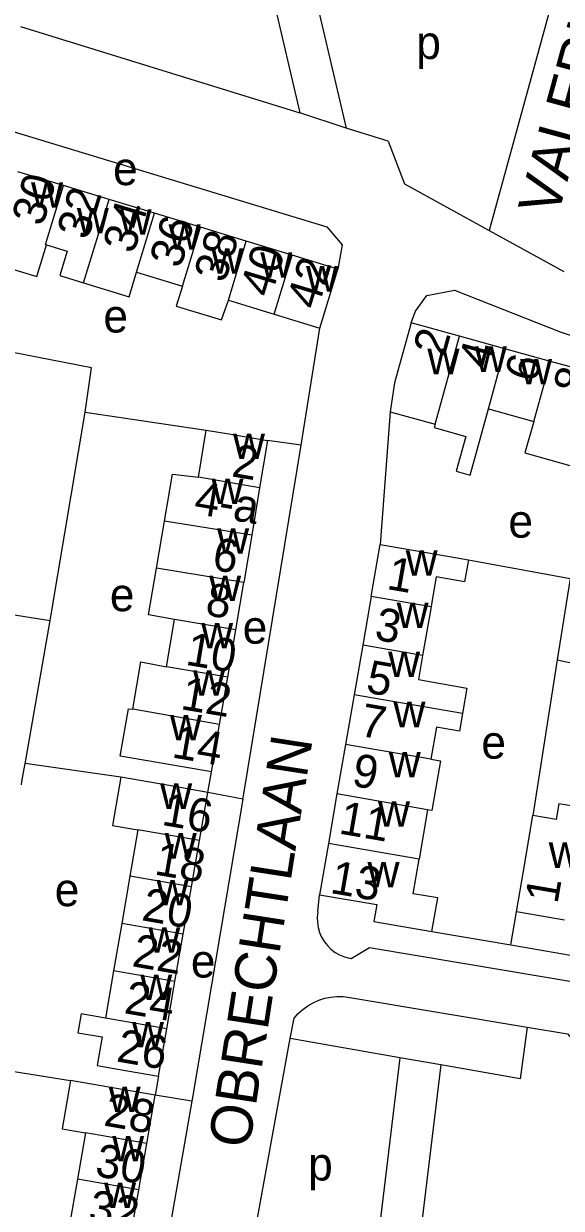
# Model space of a CAD drawing. Extents: x 159045 to 160918, y 380454 to 382516.
# Drawn here: x 160156.1 to 160221.1, y 380927 to 381070.1 of the extents above; entities that cross this region are included whole.
import ezdxf

# ---------------------------------------------------------------- set-up
doc = ezdxf.new("R2010")
doc.units = 0
for name, color, linetype in [('BLT_Basislijn', 7, 'Continuous'), ('BLT_Bebouwing', 7, 'Continuous'), ('BLT_Centroide', 7, 'Continuous'), ('BLT_Huisnummer', 7, 'Continuous'), ('BLT_Huisnummer_ tussenligend', 7, 'Continuous'), ('BLT_Huisnummer_reeks', 7, 'Continuous'), ('BLT_Onderverdeling_panden', 7, 'Continuous'), ('BLT_Straatnaam', 7, 'Continuous')]:
    doc.layers.add(name, color=color, linetype=linetype)

msp = doc.modelspace()

# ---------------------------------------------------------------- linework, layer by layer
at = {"layer": 'BLT_Basislijn'}
for p, q in [((160183.61, 381084.54), (160189.49, 381059.35)), ((160188.66, 381084.9), (160195.06, 381057.51)), ((160220.55, 381075.05), (160212.36, 381045.16)), ((160155.74, 381069.81), (160189.49, 381059.35)), ((160195.06, 381057.51), (160189.49, 381059.35)), ((160200.15, 381055.96), (160195.06, 381057.51)), ((160212.36, 381045.16), (160221.37, 381040.19)), ((160189.62, 381019.2), (160191.91, 381033.36)), ((160163.53, 381023.19), (160178.17, 381021.03)), ((160200.38, 381023.25), (160199.19, 381007.19)), ((160189.62, 381019.2), (160185.58, 381019.79)), ((160209.85, 381005.36), (160222.14, 381003.08)), ((160222.14, 381003.08), (160220.58, 380993.28)), ((160147.11, 380999.97), (160159.31, 380998)), ((160220.58, 380993.28), (160217.63, 380974.45)), ((160167.85, 380979.07), (160156.28, 380980.74)), ((160178.36, 380977.25), (160178.8, 380979.72)), ((160182.59, 380976.44), (160178.36, 380977.25)), ((160191.64, 380962.79), (160191.85, 380964.88)), ((160214.96, 380958.81), (160215.64, 380962.8)), ((160205.43, 380960.45), (160214.96, 380958.81)), ((160214.96, 380958.81), (160266.2, 380949.96)), ((160195.53, 380952.46), (160216.94, 380948.87)), ((160188.31, 380947.52), (160188.78, 380949.96)), ((160188.1, 380946.43), (160188.31, 380947.52)), ((160201.57, 380945.18), (160188.31, 380947.52)), ((160201.57, 380945.18), (160198.45, 380919.42)), ((160206.5, 380944.31), (160201.57, 380945.18)), ((160149.99, 380944.28), (160161.78, 380942.42)), ((160172.41, 380942.95), (160172, 380940.65)), ((160176.43, 380939.93), (160169.46, 380899.95)), ((160176.43, 380939.93), (160172, 380940.65))]:
    msp.add_line(p, q, dxfattribs=at)
for points in [[(160144.79, 381051.32), (160146.23, 381056.39), (160148.09, 381058.01), (160150.82, 381058.34), (160192.75, 381045.59), (160194.59, 381043.41), (160194.08, 381040.48)], [(160200.15, 381055.96), (160202.12, 381050.8), (160212.36, 381045.16)], [(160202.94, 381033.98), (160203.47, 381035.4), (160204.81, 381037.31), (160208.15, 381037.92), (160220.93, 381032.9), (160227.78, 381030.61)], [(160163.53, 381023.19), (160164.31, 381028.56), (160152.91, 381030.75)], [(160159.31, 380998), (160159.44, 380998.75), (160163.53, 381023.19)], [(160182.59, 380976.44), (160182.69, 380977.05), (160189.62, 381019.2)], [(160156.28, 380980.74), (160156.39, 380981.4), (160159.31, 380998)], [(160220.58, 380993.28), (160264.07, 380984), (160264.86, 380983.82)], [(160155.83, 380978.15), (160155.9, 380978.57), (160156.28, 380980.74)], [(160182.59, 380976.44), (160176.55, 380940.61), (160176.43, 380939.93)], [(160191.64, 380962.79), (160191.57, 380962.17), (160191.59, 380961.55), (160191.68, 380960.93), (160191.85, 380960.33), (160192.1, 380959.76), (160192.42, 380959.22), (160192.8, 380958.73), (160193.24, 380958.29), (160193.74, 380957.91), (160194.28, 380957.6), (160194.86, 380957.36), (160195.46, 380957.2), (160195.68, 380957.16)], [(160195.68, 380957.16), (160197.88, 380958.48), (160214.44, 380955.7)], [(160214.44, 380955.7), (160243.39, 380950.84), (160245.15, 380948.64), (160249.85, 380947.76), (160252.2, 380949.23), (160265.74, 380946.93)], [(160188.78, 380949.96), (160189.28, 380950.52), (160189.83, 380951.02), (160190.44, 380951.46), (160191.09, 380951.83), (160191.77, 380952.13), (160192.49, 380952.36), (160193.22, 380952.5), (160193.96, 380952.57), (160194.71, 380952.56), (160195.53, 380952.46)], [(160216.94, 380948.87), (160216.09, 380942.62), (160206.5, 380944.31)], [(160216.94, 380948.87), (160221.81, 380948.05), (160224, 380945.53)], [(160183.55, 380921.19), (160183.64, 380921.79), (160188.1, 380946.43)], [(160206.5, 380944.31), (160202.35, 380910.03), (160220.25, 380887.73), (160235.76, 380883.98), (160266.8, 380894.06), (160278.47, 380912.01), (160315.25, 380921.76), (160328.36, 380918.78), (160334.54, 380928.67)]]:
    msp.add_lwpolyline(points, dxfattribs=at)
at = {"layer": 'BLT_Bebouwing'}
for p, q in [((160160.92, 381050.58), (160155.42, 381052.25)), ((160166.42, 381048.9), (160160.92, 381050.58)), ((160171.93, 381047.23), (160166.42, 381048.9)), ((160177.47, 381045.54), (160171.93, 381047.23)), ((160183.01, 381043.85), (160177.47, 381045.54)), ((160188.55, 381042.17), (160183.01, 381043.85)), ((160194.08, 381040.48), (160188.55, 381042.17)), ((160168.85, 381037.15), (160169.76, 381040.11)), ((160169.76, 381040.11), (160175.3, 381038.42)), ((160191.91, 381033.36), (160194.08, 381040.48)), ((160163.35, 381038.83), (160168.85, 381037.15)), ((160180.84, 381036.74), (160186.38, 381035.05)), ((160186.38, 381035.05), (160191.91, 381033.36)), ((160208.75, 381032.38), (160202.94, 381033.98)), ((160214.26, 381030.85), (160208.75, 381032.38)), ((160219.77, 381029.33), (160214.26, 381030.85)), ((160200.38, 381023.25), (160205.81, 381021.75)), ((160212.26, 381023.6), (160217.74, 381022.08)), ((160177.22, 381015.32), (160178.17, 381021.03)), ((160185.58, 381019.79), (160184.62, 381014.07)), ((160184.62, 381014.07), (160183.67, 381008.34)), ((160172.17, 381004.36), (160173.14, 381010.04)), ((160183.67, 381008.34), (160182.71, 381002.61)), ((160198.11, 381000.91), (160199.19, 381007.19)), ((160205.33, 380999.66), (160204.3, 380993.77)), ((160173.36, 380992.42), (160174.34, 380998.14)), ((160180.76, 380991.16), (160181.74, 380996.89)), ((160197.07, 380995.02), (160196.04, 380989.03)), ((160179.78, 380985.44), (160180.76, 380991.16)), ((160196.04, 380989.03), (160195, 380983.04)), ((160178.8, 380979.72), (160179.78, 380985.44)), ((160195, 380983.04), (160193.96, 380977.05)), ((160177.35, 380971.42), (160178.36, 380977.25)), ((160193.96, 380977.05), (160192.92, 380971.06)), ((160204.92, 380975.15), (160203.88, 380969.16)), ((160169.92, 380972.71), (160168.95, 380967.11)), ((160176.38, 380965.82), (160177.35, 380971.42)), ((160192.92, 380971.06), (160191.85, 380964.88)), ((160168.95, 380967.11), (160167.96, 380961.39)), ((160175.38, 380960.1), (160176.38, 380965.82)), ((160221.46, 380961.8), (160215.64, 380962.8)), ((160167.96, 380961.39), (160166.97, 380955.67)), ((160174.39, 380954.38), (160175.38, 380960.1)), ((160166.97, 380955.67), (160165.98, 380949.95)), ((160173.4, 380948.67), (160174.39, 380954.38)), ((160172.41, 380942.95), (160173.4, 380948.67)), ((160170.98, 380934.81), (160172, 380940.65)), ((160163.59, 380936.09), (160162.62, 380930.49)), ((160170.01, 380929.2), (160170.98, 380934.81)), ((160162.62, 380930.49), (160161.62, 380924.77)), ((160169.02, 380923.48), (160170.01, 380929.2))]:
    msp.add_line(p, q, dxfattribs=at)
for points in [[(160152.37, 381042.25), (160152.08, 381041.29), (160157.68, 381039.59), (160158.85, 381043.43)], [(160158.85, 381043.43), (160161.37, 381042.66), (160160.47, 381039.71), (160163.35, 381038.83)], [(160175.3, 381038.42), (160174.52, 381036.02), (160180.02, 381034.35), (160180.84, 381036.74)], [(160202.94, 381033.98), (160200.93, 381026.73), (160200.38, 381023.25)], [(160217.74, 381022.08), (160216.66, 381018.26), (160222.36, 381016.68), (160224.16, 381023.05), (160225.42, 381027.77), (160219.77, 381029.33)], [(160205.81, 381021.75), (160205.7, 381021.33), (160209.53, 381020.27), (160208.36, 381016.05), (160210.04, 381015.59), (160212.26, 381023.6)], [(160178.17, 381021.03), (160180.65, 381020.61), (160185.58, 381019.79)], [(160173.14, 381010.04), (160174.1, 381015.72), (160177.22, 381015.32)], [(160199.19, 381007.19), (160204.11, 381006.34), (160209.85, 381005.36)], [(160209.85, 381005.36), (160209.39, 381002.69), (160205.95, 381003.29), (160205.39, 381000), (160205.33, 380999.66)], [(160174.34, 380998.14), (160171.21, 380998.69), (160172.17, 381004.36)], [(160181.74, 380996.89), (160182.27, 381000), (160182.71, 381002.61)], [(160198.11, 381000.91), (160197.95, 381000), (160197.07, 380995.02)], [(160169.28, 380987.29), (160170.25, 380993.01), (160173.36, 380992.42)], [(160204.3, 380993.77), (160203.8, 380990.87), (160209.65, 380989.85), (160209.12, 380986.77)], [(160178.8, 380979.72), (160173.87, 380980.57), (160167.78, 380981.63), (160168.78, 380987.36), (160169.28, 380987.29)], [(160209.12, 380986.77), (160208.75, 380984.63), (160205.99, 380985.11), (160205.32, 380981.25)], [(160205.32, 380981.25), (160206.47, 380981.05), (160205.43, 380975.06), (160204.92, 380975.15)], [(160167.85, 380979.07), (160166.84, 380973.24), (160169.92, 380972.71)], [(160178.36, 380977.25), (160173.43, 380978.1), (160167.85, 380979.07)], [(160223.49, 380973.65), (160223.78, 380975.36), (160220.77, 380975.87), (160220.44, 380973.97), (160217.63, 380974.45)], [(160215.64, 380962.8), (160216.48, 380967.73), (160217.63, 380974.45)], [(160205.43, 380960.45), (160206.13, 380964.49), (160203.16, 380965), (160203.88, 380969.16)], [(160191.85, 380964.88), (160198.77, 380963.68), (160198.4, 380961.66), (160205.43, 380960.45)], [(160165.98, 380949.95), (160163.05, 380950.48), (160162.66, 380948.2), (160165.58, 380947.69), (160164.98, 380944.24), (160167.48, 380943.8), (160172.41, 380942.95)], [(160161.78, 380942.42), (160160.77, 380936.58), (160163.59, 380936.09)], [(160172, 380940.65), (160167.07, 380941.5), (160161.78, 380942.42)]]:
    msp.add_lwpolyline(points, dxfattribs=at)
at = {"layer": 'BLT_Onderverdeling_panden'}
for p, q in [((160163.35, 381038.83), (160166.42, 381048.9)), ((160169.76, 381040.11), (160171.93, 381047.23)), ((160175.3, 381038.42), (160177.47, 381045.54)), ((160180.84, 381036.74), (160183.01, 381043.85)), ((160186.38, 381035.05), (160188.55, 381042.17)), ((160205.81, 381021.75), (160208.75, 381032.38)), ((160212.26, 381023.6), (160214.26, 381030.85)), ((160217.74, 381022.08), (160219.77, 381029.33)), ((160184.62, 381014.07), (160177.22, 381015.32)), ((160183.67, 381008.34), (160173.14, 381010.04)), ((160182.71, 381002.61), (160172.17, 381004.36)), ((160205.33, 380999.66), (160198.11, 381000.91)), ((160181.74, 380996.89), (160174.34, 380998.14)), ((160204.3, 380993.77), (160197.07, 380995.02)), ((160180.76, 380991.16), (160173.36, 380992.42)), ((160209.12, 380986.77), (160196.04, 380989.03)), ((160179.78, 380985.44), (160169.28, 380987.29)), ((160205.32, 380981.25), (160195, 380983.04)), ((160177.35, 380971.42), (160169.92, 380972.71)), ((160176.38, 380965.82), (160168.95, 380967.11)), ((160175.38, 380960.1), (160167.96, 380961.39)), ((160174.39, 380954.38), (160166.97, 380955.67)), ((160173.4, 380948.67), (160165.98, 380949.95)), ((160170.98, 380934.81), (160163.59, 380936.09)), ((160170.01, 380929.2), (160162.62, 380930.49))]:
    msp.add_line(p, q, dxfattribs=at)
for points in [[(160158.85, 381043.43), (160158.75, 381043.46), (160160.92, 381050.58)], [(160204.92, 380975.15), (160193.96, 380977.05)], [(160203.88, 380969.16), (160192.92, 380971.06)]]:
    msp.add_lwpolyline(points, dxfattribs=at)

# ---------------------------------------------------------------- texts
at = {"layer": 'BLT_Centroide'}
for s, p in [('p', (160203.54, 381065.88)), ('e', (160166.91, 381050.63)), ('w', (160157, 381047.89)), ('w', (160162.53, 381044.81)), ('w', (160167.69, 381044.64)), ('w', (160173.61, 381042.83)), ('w', (160178.77, 381039.94)), ('w', (160184.69, 381039.45)), ('w', (160190.23, 381037.77)), ('e', (160165.74, 381032.82)), ('w', (160210.61, 381028.06)), ('w', (160204.89, 381027.78)), ('w', (160216.09, 381026.56)), ('w', (160181.4, 381017.53)), ('w', (160178.81, 381012.09)), ('e', (160214.68, 381008.03)), ('w', (160179.48, 381006.09)), ('w', (160202.26, 381003.44)), ('w', (160178.52, 381000.38)), ('e', (160166.52, 380999.14)), ('w', (160201.17, 380997.12)), ('e', (160182.57, 380995.22)), ('w', (160177.55, 380994.66)), ('w', (160200.14, 380991.19)), ('w', (160176.57, 380988.94)), ('w', (160200.78, 380985.12)), ('w', (160173.78, 380983.53)), ('e', (160211.41, 380981.32)), ('w', (160200.22, 380979.06)), ('w', (160172.6, 380975.25)), ('w', (160198.92, 380973.09)), ('w', (160173.15, 380969.25)), ('w', (160219.55, 380968.12)), ('w', (160197.65, 380965.75)), ('e', (160159.86, 380963.49)), ('w', (160172.16, 380963.59)), ('w', (160171.17, 380957.88)), ('e', (160176.31, 380954.87)), ('w', (160170.19, 380952.16)), ('w', (160169.2, 380946.44)), ('w', (160166.38, 380938.62)), ('w', (160166.8, 380932.66)), ('p', (160190.48, 380930.34)), ('w', (160165.82, 380927))]:
    msp.add_text(s, height=4, dxfattribs=at).set_placement(p)
at = {"layer": 'BLT_Huisnummer'}
for s, rotation, p in [('32', 73.0677, (160163.85, 381043.9)), ('36', 73.0632, (160175.05, 381040.45)), ('42', 73.0626, (160191.62, 381035.45)), ('2', 74.5606, (160206.95, 381029.76)), ('8', 74.5599, (160223.85, 381025.12)), ('2', 350.3855, (160181.12, 381015.45)), ('6', 350.3853, (160178.75, 381004.18)), ('1', 350.1918, (160199.86, 381001.84)), ('10', 350.3828, (160175.56, 380992.69)), ('5', 350.1921, (160197.35, 380989.33)), ('14', 350.1646, (160173.9, 380981.49)), ('9', 350.1913, (160195.63, 380978.06)), ('18', 350.1615, (160171.79, 380967.34)), ('13', 350.1639, (160193.01, 380965.11)), ('1', 80.2799, (160220.6, 380963.68)), ('22', 350.1602, (160169.08, 380956.25)), ('26', 350.1533, (160167.2, 380944.75)), ('30', 350.1626, (160164.61, 380930.9))]:
    msp.add_text(s, height=4, rotation=rotation, dxfattribs=at).set_placement(p)
at = {"layer": 'BLT_Huisnummer_ tussenligend'}
for s, rotation, p in [('30', 73.0699, (160158.39, 381045.54)), ('34', 73.0677, (160169.4, 381042.22)), ('38', 73.0632, (160180.42, 381038.7)), ('40', 73.0632, (160185.99, 381036.93)), ('4', 74.5606, (160212.42, 381028.2)), ('6', 74.5606, (160218, 381026.65)), ('8', 350.3853, (160177.93, 380998.7)), ('3', 350.1918, (160198.38, 380995.72)), ('12', 350.3828, (160174.96, 380987.32)), ('7', 350.1921, (160196.58, 380984.1)), ('16', 350.1646, (160172.67, 380973.33)), ('11', 350.1913, (160194.07, 380972.29)), ('20', 350.1615, (160170.25, 380961.81)), ('24', 350.1602, (160168.13, 380950.58)), ('28', 350.1533, (160165.66, 380937)), ('32', 350.1626, (160163.8, 380925.32))]:
    msp.add_text(s, height=4, rotation=rotation, dxfattribs=at).set_placement(p)
at = {"layer": 'BLT_Huisnummer_reeks'}
msp.add_text('4-a', height=4, rotation=350.3897, dxfattribs=at).set_placement((160176.56, 381010.95))
at = {"layer": 'BLT_Straatnaam'}
for s, height, rotation, p in [('VALERIUSSTRAAT', 5, 74.7717, (160220.62, 381046.68)), ('OBRECHTLAAN', 4.9999, 81.1927, (160183.35, 380934.1))]:
    msp.add_text(s, height=height, rotation=rotation, dxfattribs=at).set_placement(p)

doc.saveas('drawing.dxf')
